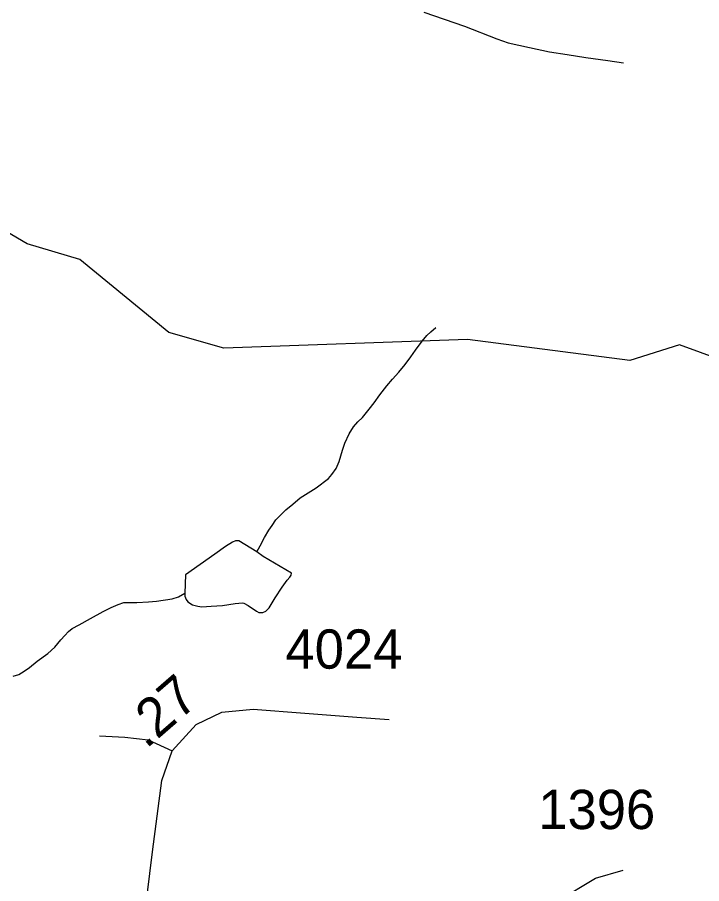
# Model space of a CAD drawing. Extents: x 2001466 to 2224147, y 644118 to 847247.
# Drawn here: x 2053478 to 2055654, y 684326 to 687083 of the extents above; entities that cross this region are included whole.
import ezdxf

# ---------------------------------------------------------------- set-up
doc = ezdxf.new("R2010")
doc.units = 0
for name, color, linetype in [('Exist Hydrographic Misc Water Feature', 7, 'Continuous'), ('Exist Road Non-System Type 51', 7, 'Continuous'), ('Exist Road Secondary Mileage Hundredths English Label', 7, 'Continuous'), ('Exist Road Secondary Type 51 Attributed', 7, 'Continuous'), ('Exist Road Secondary Type 51 Number Label', 7, 'Continuous')]:
    doc.layers.add(name, color=color, linetype=linetype)

msp = doc.modelspace()

# ---------------------------------------------------------------- linework, layer by layer
at = {"layer": 'Exist Hydrographic Misc Water Feature'}
for points in [[(2057175.8, 685650.5), (2057092.8, 685625.9), (2056800.8, 685641.7), (2056092.9, 685816.9), (2055933.8, 685807), (2055716.9, 685991.8), (2055583.8, 686040.5), (2055425.9, 685991.2), (2054908.9, 686057.5), (2054133.9, 686030.6), (2053958.9, 686080.1), (2053676, 686312.3), (2053508.9, 686361.6), (2053392, 686429.6), (2053104.9, 686514.2)], [(2054239.7, 685381.5), (2054249.7, 685401.4), (2054263.9, 685427.2), (2054277.6, 685451.1), (2054287.6, 685465.4), (2054299.5, 685483.5), (2054315.3, 685499.3), (2054331.7, 685515.5), (2054353.3, 685533.4), (2054377.5, 685553.6), (2054427.5, 685585.4), (2054467.5, 685615.8), (2054477.5, 685627.7), (2054491.5, 685647.5), (2054500.9, 685669.5), (2054511.4, 685705.7), (2054518.7, 685727.7), (2054533.1, 685757.5), (2054547, 685779.8), (2054560.8, 685795.6), (2054574.9, 685809.6), (2054596.7, 685835.9), (2054612.9, 685855.8), (2054630.7, 685881.8), (2054652.4, 685909.8), (2054670.5, 685931.8), (2054690.4, 685954), (2054710.5, 685978.1), (2054728.5, 686002.1), (2054744.1, 686024.1), (2054764.6, 686052.2), (2054780.4, 686070.1), (2054792.1, 686082.1), (2054808.5, 686096.3)], [(2054239.7, 685381.5), (2054181.8, 685417), (2054171.6, 685416.9), (2054161.5, 685413.1), (2054139.6, 685399), (2054106, 685375), (2054012.1, 685308.9), (2054010, 685250.8)], [(2054010, 685250.8), (2054010, 685240.6), (2054014.3, 685230.6), (2054020.3, 685222.9), (2054034.2, 685213), (2054051.8, 685209.1), (2054064.3, 685206.9), (2054093.9, 685208.9), (2054130, 685211.1), (2054170.1, 685217.2), (2054193.9, 685219.2), (2054198, 685219), (2054212, 685211.2), (2054238, 685193.1), (2054245.8, 685189.4), (2054252.2, 685189.3), (2054258.1, 685189.2), (2054268.2, 685193.4), (2054278, 685203.3), (2054297.7, 685235.5), (2054320, 685269.5), (2054336, 685291.4), (2054344, 685301.5), (2054347.9, 685307.4), (2054349.8, 685313.6), (2054259.8, 685367.4), (2054239.7, 685381.5)], [(2053464.8, 684985.9), (2053482.8, 684992), (2053498.8, 685001.8), (2053516.6, 685014.1), (2053540.2, 685034), (2053574.5, 685058), (2053596.6, 685078.2), (2053616.3, 685102), (2053628.4, 685116), (2053640.1, 685128), (2053652, 685138.3), (2053674.3, 685150), (2053710, 685170.1), (2053750.4, 685192.4), (2053776, 685204.3), (2053798.2, 685214.3), (2053816.2, 685220.5), (2053828.1, 685220.3), (2053857.9, 685220.7), (2053894.4, 685222.5), (2053920.2, 685224.6), (2053970, 685232.9), (2053989.7, 685238.8), (2054010, 685250.8)]]:
    msp.add_lwpolyline(points, dxfattribs=at)
at = {"layer": 'Exist Road Non-System Type 51'}
for points in [[(2054770.5, 687099.6), (2054899.6, 687054.9), (2055002.8, 687014.8), (2055038.5, 687002.1), (2055106.2, 686986.7), (2055169.9, 686973.4), (2055225.7, 686964.3), (2055285.5, 686955.1), (2055355.3, 686945.7), (2055405.2, 686938.6)], [(2053738.9, 684795.9), (2053819.5, 684791.9), (2053894.1, 684783.8), (2053970.1, 684748.9)]]:
    msp.add_lwpolyline(points, dxfattribs=at)
at = {"layer": 'Exist Road Secondary Type 51 Attributed'}
for points in [[(2053873.8, 684151.2), (2053907, 684426.8), (2053936.9, 684654.2), (2053970.1, 684748.9), (2054045.8, 684832.6), (2054127.9, 684872.1), (2054227.3, 684881.5), (2054391.4, 684868.9), (2054557.1, 684856.3), (2054659.6, 684848.4)], [(2053873.8, 684151.2), (2054129.5, 684129.1), (2054296.7, 684122.8), (2054530.2, 684122.8), (2054713.3, 684132.3), (2054804.8, 684135.5), (2054908.9, 684151.2), (2055044.6, 684198.6), (2055196.1, 684271.2), (2055316, 684343.9), (2055404.4, 684369.1)]]:
    msp.add_lwpolyline(points, dxfattribs=at)

# ---------------------------------------------------------------- texts
at = {"layer": 'Exist Road Secondary Mileage Hundredths English Label'}
msp.add_text('.27', height=125, rotation=40.9605, dxfattribs=at).set_placement((2053887, 684752.9))
at = {"layer": 'Exist Road Secondary Type 51 Number Label'}
for s, p in [('4024', (2054330.3, 685010.1)), ('1396', (2055134.5, 684499.6))]:
    msp.add_text(s, height=125, dxfattribs=at).set_placement(p)

doc.saveas('drawing.dxf')
